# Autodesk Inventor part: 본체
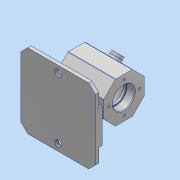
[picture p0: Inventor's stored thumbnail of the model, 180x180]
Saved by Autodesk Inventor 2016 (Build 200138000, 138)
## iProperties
Created: 2018-06
Part Number: 본체
Material: 알루미늄 6061
Document SubType Name: Modeling
Designer: 602-10
Density: 2.7 g/cm^3
Appearance: 알루미늄 - 평지
Mass: 551.738 g
Surface Area: 602.495 cm^2
Volume: 204.347 cm^3
Author: 602-10
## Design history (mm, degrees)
sketch "스케치1"
  geometry: L1 (55, -55)-(-55, -55); L2 (-55, -55)-(-55, 55); L3 (-55, 55)-(55, 55); L4 (55, 55)-(55, -55); L5 (55, -55)-(-55, 55); L6 (-55, -55)-(55, 55); 1 further point
  constraints: 12 end point, 2 midpoint, 2 parallel, 1 horizontal, 1 perpendicular
  dimensions: "d0" = 110 distance of L1.end L2.end; "d1" = 110 distance of L1.start L1.end
extrude "돌출1" new body sketch "스케치1" distance "d2" = 5; taper "d3" = 0 deg
chamfer "모따기1" distance "d4" = 10; stored, may be unused: second distance "d5" = 2, angle "d6" = 45 deg
sketch "스케치3"
  geometry: L1 (55, -45)-(55, 45) reference; L2 (-55, 25)-(55, 25); L3 (55, 25)-(55, -25); L4 (55, -25)-(-55, -25); L5 (-55, -25)-(-55, 25); L6 (-55, 25)-(55, -25); L7 (55, 25)-(-55, -25); L8 (45, 55)-(-45, 55) reference; 1 further point
  constraints: 12 end point, 2 midpoint, 2 parallel, 1 horizontal, 1 perpendicular, 1 point on line
  dimensions: "d11" = 30 distance between parallel lines of L8 L2
extrude "돌출3" join sketch "스케치3" distance "d12" = 5; taper "d13" = 0 deg
sketch "스케치4"
  geometry: L1 (-55, 45)-(-55, 25) reference; L2 (45, 55)-(-45, 55) reference; L3 (-45, -55)-(45, -55) reference; C1 r 5 at (0, 45); C2 r 5 at (0, -45); 1 further point
  constraints: 2 centre point, 1 vertical alignment
  dimensions: "d14" = 10 diameter of C1; "d15" = 55 distance from line of L1 C1.centre; "d16" = 10 distance from line of C1.centre L2; "d17" = 10 distance from line of L3 C2.centre; "d18" = 10 diameter of C2
extrude "돌출4" cut sketch "스케치4" stored distance "d19" = 5; taper "d20" = 0 deg
sketch "스케치5"
  geometry: L1 (0, 45)-(0, -45) reference; L2 (10, -25)-(10, 25) reference; L3 (32, 12.426)-(49.574, 30); L4 (49.574, 30)-(74.426, 30); L5 (74.426, 30)-(92, 12.426); L6 (92, 12.426)-(92, -12.426); L7 (92, -12.426)-(74.426, -30); L8 (74.426, -30)-(49.574, -30); L9 (49.574, -30)-(32, -12.426); L10 (32, -12.426)-(32, 12.426); 5 further points
  constraints: 16 end point, 3 midpoint, 1 horizontal alignment, 1 vertical, 17 other
  dimensions: "d24" = 62 distance from line of L1 point (62, 0); "d25" = 92 distance between parallel lines of L1 L6
extrude "돌출5" join sketch "스케치5" stored distance "d27" = 70; taper "d28" = 0 deg
sketch "스케치6"
  geometry: L1 (19, 0)-(-19, 0); L2 (19, 5)-(-19, 5); L3 (-19, -5)-(19, -5); A1 r 5 centre (19, 0) between (19, -5) and (19, 5); A2 r 5 centre (-19, 0) between (-19, 5) and (-19, -5); 1 further point
  constraints: 8 end point, 4 point on circle, 4 tangent, 2 centre point, 1 horizontal, 1 midpoint, 1 parallel
  dimensions: "d29" = 5 radius of A1; "d30" = 38 distance of L1.end L1.start
extrude "돌출6" join sketch "스케치6" stored distance "d31" = 70; taper "d32" = 0 deg
fillet "모깎기1" dims "d33" = 2
sketch "스케치7"
  geometry: L1 (70, 24.853)-(70, 0) reference; C1 r 8 at (35, 12.426); 2 further points
  constraints: 1 centre point, 1 horizontal alignment, 1 midpoint, 1 vertical alignment
  dimensions: "d34" = 16 diameter of C1
extrude "돌출7" join sketch "스케치7" distance "d35" = 7; taper "d36" = 0 deg
fillet "모깎기2" dims "d37" = 3
sketch "스케치8"
  geometry: L1 (45, 0)-(-45, 0) reference; C1 r 16 at (0, 62); 2 further points
  constraints: 1 centre point, 1 midpoint, 1 vertical alignment
  dimensions: "d38" = 32 diameter of C1; "d39" = 62 distance from line of L1 C1.centre
extrude "돌출8" cut sketch "스케치8" distance "d40" = 12; taper "d41" = 0 deg
sketch "스케치9"
  geometry: L1 (45, -62)-(-45, -62) reference; C1 r 14 at (0, 0); 2 further points
  constraints: 1 centre point, 1 midpoint, 1 vertical alignment
  dimensions: "d42" = 28 diameter of C1; "d43" = 62 distance from line of L1 C1.centre
extrude "돌출9" cut sketch "스케치9" distance "d44" = 3; taper "d45" = 0 deg
sketch "스케치10"
  geometry: L1 (-45, -62)-(45, -62) reference; C1 r 25 at (0, 0); 1 further point
  constraints: 1 centre point, 1 vertical alignment
  dimensions: "d46" = 50 diameter of C1; "d47" = 62 distance from line of L1 C1.centre
extrude "돌출10" cut sketch "스케치10" distance "d48" = 40; taper "d49" = 0 deg
sketch "스케치11"
  geometry: L1 (45, 0)-(-45, 0) reference; C1 r 16 at (0, 62); 2 further points
  constraints: 1 centre point, 1 midpoint, 1 vertical alignment
  dimensions: "d50" = 32 diameter of C1; "d51" = 62 distance from line of L1 C1.centre
extrude "돌출11" cut sketch "스케치11" distance "d52" = 12; taper "d53" = 0 deg
sketch "스케치12"
  geometry: L1 (45, -62)-(-45, -62) reference; C1 r 14 at (0, 0); 2 further points
  constraints: 1 centre point, 1 midpoint, 1 vertical alignment
  dimensions: "d54" = 28 diameter of C1; "d55" = 62 distance from line of L1 C1.centre
extrude "돌출12" cut sketch "스케치12" distance "d56" = 3; taper "d57" = 0 deg
node "작업 평면1"
sketch "스케치13"
  geometry: L1 (0, 24.853)-(0, 42.426) reference; L2 (70, 42.426)-(0, 42.426) reference; 2 further points
  constraints: 1 other
  dimensions: "d59" = 35 distance from line of L1 point (35, 12.426); "d60" = 30 distance from line of L2 point (35, 12.426)
feature "엠보싱1" sketch "스케치13" dims "d0" = 110, "d1" = 110, "d61" = 0.5, "d62" = 0
sketch "스케치14"
  geometry: L1 (35, 12.426)-(35, -12.426) reference; C1 r 4 at (0, 0); 2 further points
  constraints: 1 centre point, 1 horizontal alignment, 1 midpoint, 1 vertical alignment
  dimensions: "d63" = 8 diameter of C1
extrude "돌출13" cut sketch "스케치14" distance "d64" = 30; taper "d65" = 0 deg
chamfer "모따기2" distance "d66" = 1; stored, may be unused: second distance "d67" = 2, angle "d68" = 45 deg
fillet "모깎기3" dims "d69" = 0.3
fillet "모깎기4" dims "d70" = 3
sketch "스케치15" dims "d71" = 46
  geometry: C1 r 14 at (0, 62) reference; 3 further points
  constraints: 2 vertical alignment, 3 other
hole "구멍1" sketch "스케치15" at (0, 85) diameter "d72" = 3.459; stored, may be unused: countersink angle "d76" = 90 deg, drill point angle "d78" = 118 deg; dims "d73" = 8, "d74" = 4, "d75" = 2, "d77" = 10
fillet "모깎기5" dims "d82" = 1
node "솔리드1"
pattern_circular "원형 패턴1" dims angle "d80" = 360 deg
mirror "대칭1"
other parameters: "d58" = 27
